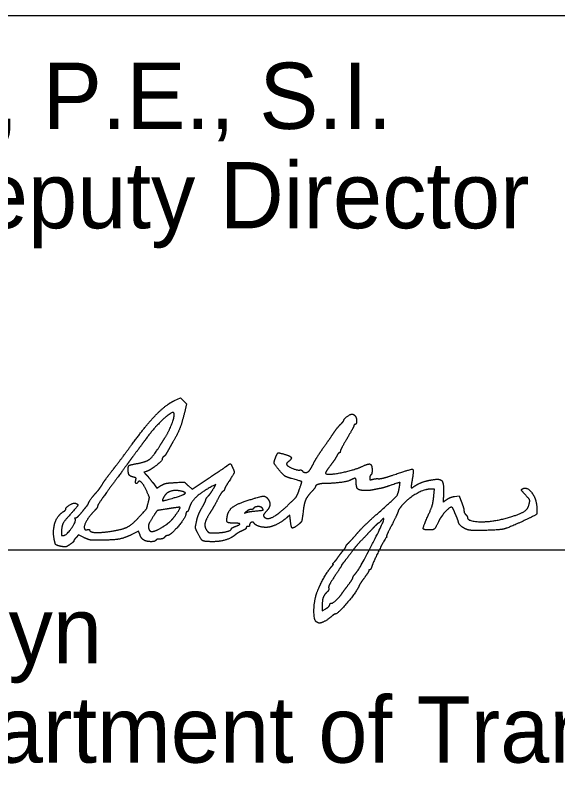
# Model space of a CAD drawing. Extents: x 0 to 42, y 0 to 22.
# Drawn here: x 25.676 to 26.824, y 7.305 to 8.926 of the extents above; entities that cross this region are included whole.
import ezdxf

# ---------------------------------------------------------------- set-up
doc = ezdxf.new("R2010")
doc.units = 0
doc.layers.add('SH_Data', color=7, linetype='Continuous')
doc.layers.add('SH_Text', color=7, linetype='Continuous')

msp = doc.modelspace()

# ---------------------------------------------------------------- linework, layer by layer
at = {"layer": 'SH_Data'}
for p, q in [((24.5279, 8.9262), (28.0279, 8.9262)), ((24.5279, 7.7968), (28.0279, 7.7968))]:
    msp.add_line(p, q, dxfattribs=at)
at = {"layer": 'SH_Text'}
for points in [[(26.0131, 8.112), (26.0258, 8.1179), (26.0321, 8.1115), (26.0385, 8.1051), (26.0341, 8.0864)], [(25.9532, 7.962), (25.9482, 7.9605), (25.9534, 7.9553)], [(26.0422, 7.9323), (26.0503, 7.9247), (26.0866, 7.9488)], [(25.967, 7.9386), (25.9756, 7.9271), (25.9844, 7.9323)], [(26.0961, 7.9271), (26.1005, 7.935), (26.095, 7.9321)], [(26.5619, 7.9112), (26.5634, 7.925), (26.5556, 7.925)], [(26.6058, 7.9095), (26.6154, 7.9111), (26.6205, 7.8975)], [(26.2578, 7.8634), (26.2572, 7.8702), (26.2513, 7.8651)], [(25.9402, 7.8278), (25.9369, 7.8358), (25.923, 7.829)], [(25.8216, 7.8227), (25.8101, 7.8285), (25.805, 7.8227)], [(26.3256, 7.6773), (26.3256, 7.6679), (26.3331, 7.6722)]]:
    msp.add_lwpolyline(points, dxfattribs=at)
for points in [[(25.9236, 8.0201), (25.9533, 8.0607), (25.9951, 8.1036), (26.0131, 8.112)], [(26.0117, 8.0862), (26.008, 8.0899), (25.9695, 8.0541), (25.9541, 8.0328)], [(25.9934, 8.0342), (26.0028, 8.049), (26.0148, 8.0831), (26.0117, 8.0862)], [(26.0341, 8.0864), (26.0291, 8.0653), (26.0199, 8.0417), (26.0105, 8.0258)], [(26.3712, 8.0701), (26.3712, 8.0729), (26.3844, 8.0832), (26.3881, 8.0833)], [(26.3881, 8.0833), (26.3901, 8.0833), (26.3931, 8.0821), (26.3947, 8.0805)], [(26.3947, 8.0805), (26.3982, 8.077), (26.3986, 8.0618), (26.3952, 8.0618)], [(26.3508, 8.0448), (26.3547, 8.0506), (26.361, 8.0583), (26.3646, 8.062)], [(26.3646, 8.062), (26.3682, 8.0656), (26.3712, 8.0693), (26.3712, 8.0701)], [(26.3952, 8.0618), (26.3939, 8.0618), (26.3928, 8.0606), (26.3928, 8.0592)], [(26.3292, 8.0138), (26.3371, 8.025), (26.3468, 8.0389), (26.3508, 8.0448)], [(26.3928, 8.0592), (26.3928, 8.0579), (26.3863, 8.0458), (26.3784, 8.0324)], [(25.9541, 8.0328), (25.9505, 8.0279), (25.9411, 8.0152), (25.9332, 8.0047)], [(25.9829, 8.0175), (25.9861, 8.0227), (25.9909, 8.0302), (25.9934, 8.0342)], [(26.3784, 8.0324), (26.3705, 8.019), (26.364, 8.0066), (26.364, 8.0049)], [(25.8834, 7.9667), (25.8923, 7.978), (25.9104, 8.0021), (25.9236, 8.0201)], [(25.9331, 7.9788), (25.9537, 7.9826), (25.9677, 7.9935), (25.9829, 8.0175)], [(26.0105, 8.0258), (26.007, 8.0198), (26.0018, 8.0106), (25.9989, 8.0054)], [(26.3078, 7.9802), (26.3116, 7.9874), (26.3212, 8.0025), (26.3292, 8.0138)], [(25.9332, 8.0047), (25.9253, 7.9942), (25.9172, 7.9832), (25.9152, 7.9803)], [(25.9989, 8.0054), (25.9961, 8.0001), (25.9923, 7.9949), (25.9905, 7.9938)], [(26.2271, 7.992), (26.2309, 8.0011), (26.234, 8.0021), (26.2467, 7.9983)], [(26.2467, 7.9983), (26.2587, 7.9948), (26.2616, 7.9886), (26.2539, 7.9828)], [(26.3567, 7.9952), (26.3549, 7.9915), (26.3488, 7.9824), (26.3431, 7.975)], [(26.362, 8.0018), (26.3609, 8.0018), (26.3585, 7.9988), (26.3567, 7.9952)], [(26.364, 8.0049), (26.364, 8.0032), (26.3631, 8.0018), (26.362, 8.0018)], [(25.9152, 7.9803), (25.9132, 7.9773), (25.8978, 7.9564), (25.881, 7.9337)], [(25.9152, 7.9667), (25.9152, 7.9736), (25.9193, 7.9764), (25.9331, 7.9788)], [(25.9872, 7.9884), (25.9872, 7.9847), (25.9614, 7.9646), (25.9532, 7.962)], [(25.9905, 7.9938), (25.9887, 7.9928), (25.9872, 7.9904), (25.9872, 7.9884)], [(26.1257, 7.9753), (26.1302, 7.9791), (26.1326, 7.9782), (26.1356, 7.9716)], [(26.2369, 7.9626), (26.2254, 7.9757), (26.2232, 7.9824), (26.2271, 7.992)], [(26.2539, 7.9828), (26.2512, 7.9807), (26.2497, 7.9778), (26.2506, 7.9765)], [(26.2985, 7.964), (26.2998, 7.9656), (26.304, 7.9729), (26.3078, 7.9802)], [(25.8619, 7.9373), (25.8648, 7.9421), (25.8745, 7.9553), (25.8834, 7.9667)], [(25.9262, 7.9503), (25.919, 7.9521), (25.9152, 7.9578), (25.9152, 7.9667)], [(26.0866, 7.9488), (26.1065, 7.9621), (26.1241, 7.974), (26.1257, 7.9753)], [(26.1356, 7.9716), (26.14, 7.962), (26.139, 7.9579), (26.1288, 7.942)], [(26.2604, 7.9474), (26.2496, 7.9506), (26.2447, 7.9537), (26.2369, 7.9626)], [(26.2506, 7.9765), (26.2533, 7.9727), (26.2732, 7.9645), (26.2778, 7.9653)], [(26.2778, 7.9653), (26.2801, 7.9657), (26.2827, 7.9649), (26.2835, 7.9635)], [(26.2835, 7.9635), (26.2857, 7.96), (26.2957, 7.9603), (26.2985, 7.964)], [(26.3431, 7.975), (26.3374, 7.9675), (26.3328, 7.9602), (26.3328, 7.9589)], [(26.3328, 7.9589), (26.3328, 7.9536), (26.3924, 7.9646), (26.4104, 7.9731)], [(26.4104, 7.9731), (26.4233, 7.9793), (26.4312, 7.9762), (26.4312, 7.9648)], [(26.4312, 7.9648), (26.4312, 7.9602), (26.4301, 7.9558), (26.4288, 7.955)], [(26.4735, 7.954), (26.5139, 7.9679), (26.5198, 7.9663), (26.5157, 7.9424)], [(25.9313, 7.9441), (25.9322, 7.9476), (25.9309, 7.9491), (25.9262, 7.9503)], [(25.9534, 7.9553), (25.9562, 7.9525), (25.9623, 7.945), (25.967, 7.9386)], [(26.2772, 7.9237), (26.2828, 7.9405), (26.2825, 7.9411), (26.2604, 7.9474)], [(26.3976, 7.9396), (26.3976, 7.9469), (26.3939, 7.9485), (26.3861, 7.9443)], [(26.4288, 7.955), (26.4275, 7.9541), (26.4264, 7.9513), (26.4264, 7.9487)], [(26.4264, 7.9487), (26.4264, 7.9447), (26.4274, 7.9442), (26.4318, 7.9456)], [(26.4318, 7.9456), (26.4348, 7.9465), (26.4406, 7.9472), (26.4447, 7.947)], [(26.4447, 7.947), (26.4489, 7.9468), (26.4618, 7.95), (26.4735, 7.954)], [(25.8456, 7.9154), (25.8522, 7.9228), (25.8564, 7.9285), (25.8619, 7.9373)], [(25.881, 7.9337), (25.8643, 7.9111), (25.8505, 7.8909), (25.8504, 7.889)], [(25.9355, 7.9393), (25.9331, 7.9354), (25.9299, 7.9389), (25.9313, 7.9441)], [(25.9543, 7.9207), (25.9482, 7.9344), (25.9385, 7.944), (25.9355, 7.9393)], [(25.9844, 7.9323), (25.9909, 7.9362), (25.9985, 7.9379), (26.0136, 7.9388)], [(26.0136, 7.9388), (26.0339, 7.94), (26.0341, 7.9399), (26.0422, 7.9323)], [(26.095, 7.9321), (26.0716, 7.9195), (26.0488, 7.8989), (26.0447, 7.8864)], [(26.1288, 7.942), (26.1235, 7.9339), (26.1192, 7.9263), (26.1192, 7.9252)], [(26.3354, 7.937), (26.3239, 7.937), (26.3112, 7.9332), (26.3112, 7.9298)], [(26.3861, 7.9443), (26.3806, 7.9413), (26.3504, 7.937), (26.3354, 7.937)], [(26.4169, 7.922), (26.4045, 7.922), (26.3976, 7.9283), (26.3976, 7.9396)], [(26.4682, 7.9321), (26.4604, 7.9294), (26.4507, 7.9266), (26.4468, 7.926)], [(26.4888, 7.9274), (26.4909, 7.9389), (26.4891, 7.9393), (26.4682, 7.9321)], [(26.5157, 7.9424), (26.5143, 7.9348), (26.5136, 7.9282), (26.5141, 7.9277)], [(26.5141, 7.9277), (26.5145, 7.9272), (26.5179, 7.929), (26.5216, 7.9316)], [(26.5216, 7.9316), (26.5289, 7.9366), (26.5471, 7.9429), (26.5608, 7.9451)], [(26.5608, 7.9451), (26.5754, 7.9474), (26.5831, 7.937), (26.5823, 7.9157)], [(25.8312, 7.895), (25.8312, 7.8966), (25.8403, 7.9096), (25.8456, 7.9154)], [(25.9576, 7.8962), (25.9602, 7.906), (25.9599, 7.9082), (25.9543, 7.9207)], [(26.0254, 7.921), (26.0145, 7.9232), (25.9971, 7.9181), (25.9928, 7.9115)], [(26.0148, 7.9075), (26.034, 7.9134), (26.038, 7.9185), (26.0254, 7.921)], [(26.0833, 7.9089), (26.0887, 7.9149), (26.0912, 7.9185), (26.0961, 7.9271)], [(26.1156, 7.9202), (26.1137, 7.9186), (26.1106, 7.9144), (26.1087, 7.9109)], [(26.1192, 7.9252), (26.1192, 7.9241), (26.1176, 7.9218), (26.1156, 7.9202)], [(26.2589, 7.8964), (26.2693, 7.9064), (26.2734, 7.9126), (26.2772, 7.9237)], [(26.3018, 7.9177), (26.2933, 7.9083), (26.2876, 7.8957), (26.286, 7.883)], [(26.3112, 7.9298), (26.3112, 7.9289), (26.307, 7.9235), (26.3018, 7.9177)], [(26.4336, 7.9234), (26.4303, 7.9226), (26.4228, 7.922), (26.4169, 7.922)], [(26.4468, 7.926), (26.4428, 7.9253), (26.4369, 7.9242), (26.4336, 7.9234)], [(26.4439, 7.8744), (26.4795, 7.906), (26.4864, 7.9142), (26.4888, 7.9274)], [(26.5556, 7.925), (26.5429, 7.925), (26.5091, 7.9065), (26.4969, 7.893)], [(26.5823, 7.9157), (26.5816, 7.8973), (26.5815, 7.8976), (26.5892, 7.9031)], [(26.7524, 7.9163), (26.7471, 7.922), (26.7468, 7.9247), (26.7515, 7.9264)], [(26.7515, 7.9264), (26.76, 7.9297), (26.7785, 7.9048), (26.7795, 7.8885)], [(26.7615, 7.8872), (26.7655, 7.899), (26.7639, 7.9039), (26.7524, 7.9163)], [(25.9928, 7.9115), (25.9858, 7.9008), (25.9903, 7.9), (26.0148, 7.9075)], [(26.0708, 7.8848), (26.0752, 7.8925), (26.079, 7.9002), (26.0793, 7.9019)], [(26.0793, 7.9019), (26.0796, 7.9037), (26.0813, 7.9068), (26.0833, 7.9089)], [(26.1087, 7.9109), (26.1006, 7.8955), (26.0928, 7.8817), (26.0867, 7.872)], [(26.1249, 7.8681), (26.1271, 7.8794), (26.1433, 7.8928), (26.1626, 7.8992)], [(26.1626, 7.8992), (26.1944, 7.9098), (26.2078, 7.9102), (26.2129, 7.9008)], [(26.2129, 7.9008), (26.2161, 7.8947), (26.2127, 7.8833), (26.2053, 7.8754)], [(26.5472, 7.8633), (26.5563, 7.8832), (26.5603, 7.8964), (26.5619, 7.9112)], [(26.5892, 7.9031), (26.593, 7.9058), (26.6004, 7.9087), (26.6058, 7.9095)], [(26.6205, 7.8975), (26.6233, 7.8901), (26.6256, 7.8819), (26.6256, 7.8794)], [(25.7785, 7.8776), (25.7811, 7.8792), (25.7832, 7.8816), (25.7832, 7.8829)], [(25.7832, 7.8829), (25.7833, 7.8867), (25.8, 7.8967), (25.8038, 7.8952)], [(25.8038, 7.8952), (25.8098, 7.8929), (25.8075, 7.888), (25.7932, 7.8721)], [(25.8167, 7.8758), (25.822, 7.8824), (25.8275, 7.8891), (25.8288, 7.8907)], [(25.8288, 7.8907), (25.8301, 7.8923), (25.8312, 7.8942), (25.8312, 7.895)], [(25.8504, 7.889), (25.8503, 7.887), (25.847, 7.8822), (25.843, 7.8782)], [(25.938, 7.8657), (25.9541, 7.8832), (25.9544, 7.8838), (25.9576, 7.8962)], [(25.9956, 7.8827), (25.9778, 7.8801), (25.9758, 7.879), (25.9685, 7.8678)], [(26.013, 7.8854), (26.0074, 7.8845), (25.9995, 7.8833), (25.9956, 7.8827)], [(26.018, 7.8737), (26.0258, 7.8851), (26.0249, 7.8872), (26.013, 7.8854)], [(26.0447, 7.8864), (26.043, 7.8812), (26.0407, 7.877), (26.0396, 7.877)], [(26.0599, 7.857), (26.0615, 7.8647), (26.0664, 7.8772), (26.0708, 7.8848)], [(26.1747, 7.8818), (26.1724, 7.8818), (26.1684, 7.88), (26.1658, 7.878)], [(26.1802, 7.8839), (26.1795, 7.8827), (26.177, 7.8818), (26.1747, 7.8818)], [(26.1987, 7.885), (26.1959, 7.8884), (26.1825, 7.8876), (26.1802, 7.8839)], [(26.1828, 7.8786), (26.1995, 7.8801), (26.2019, 7.8811), (26.1987, 7.885)], [(26.2019, 7.8675), (26.2072, 7.8589), (26.2339, 7.8724), (26.2589, 7.8964)], [(26.286, 7.883), (26.2832, 7.8605), (26.2814, 7.855), (26.2758, 7.8505)], [(26.4969, 7.893), (26.4911, 7.8865), (26.4864, 7.88), (26.4864, 7.8784)], [(26.5988, 7.8866), (26.5945, 7.8866), (26.5762, 7.8661), (26.5715, 7.8559)], [(26.6044, 7.88), (26.6029, 7.8836), (26.6004, 7.8866), (26.5988, 7.8866)], [(26.7126, 7.863), (26.7363, 7.8692), (26.7593, 7.8806), (26.7615, 7.8872)], [(26.7795, 7.8885), (26.7804, 7.8732), (26.7778, 7.8701), (26.7544, 7.8591)], [(25.7583, 7.8213), (25.7554, 7.8398), (25.7661, 7.8699), (25.7785, 7.8776)], [(25.7932, 7.8721), (25.7795, 7.857), (25.7745, 7.8468), (25.7739, 7.833)], [(25.8044, 7.8645), (25.8058, 7.8641), (25.8113, 7.8692), (25.8167, 7.8758)], [(25.843, 7.8782), (25.8332, 7.8686), (25.8208, 7.8465), (25.8226, 7.8418)], [(25.8815, 7.8363), (25.9042, 7.84), (25.9238, 7.8502), (25.938, 7.8657)], [(25.9685, 7.8678), (25.9603, 7.8551), (25.9571, 7.8453), (25.9593, 7.8395)], [(25.9881, 7.845), (25.9993, 7.852), (26.0102, 7.8626), (26.018, 7.8737)], [(26.0375, 7.874), (26.0374, 7.8654), (26.0043, 7.8266), (25.9972, 7.8266)], [(26.0396, 7.877), (26.0385, 7.877), (26.0376, 7.8756), (26.0375, 7.874)], [(26.0867, 7.872), (26.0787, 7.8594), (26.0765, 7.8442), (26.0816, 7.8374)], [(26.1385, 7.853), (26.127, 7.853), (26.1229, 7.8575), (26.1249, 7.8681)], [(26.1658, 7.878), (26.1612, 7.8742), (26.1612, 7.8742), (26.166, 7.8759)], [(26.166, 7.8759), (26.1686, 7.8768), (26.1762, 7.878), (26.1828, 7.8786)], [(26.2053, 7.8754), (26.2025, 7.8725), (26.201, 7.869), (26.2019, 7.8675)], [(26.2513, 7.8651), (26.2419, 7.8569), (26.2219, 7.8463), (26.2128, 7.8446)], [(26.3999, 7.8317), (26.4071, 7.8401), (26.4269, 7.8593), (26.4439, 7.8744)], [(26.4864, 7.8784), (26.4864, 7.8768), (26.4804, 7.864), (26.4732, 7.8498)], [(26.6103, 7.8658), (26.6085, 7.87), (26.6058, 7.8763), (26.6044, 7.88)], [(26.6137, 7.8562), (26.6136, 7.8573), (26.6121, 7.8616), (26.6103, 7.8658)], [(26.6256, 7.8794), (26.6256, 7.8769), (26.6272, 7.8733), (26.6292, 7.8713)], [(26.6292, 7.8713), (26.6312, 7.8693), (26.6328, 7.8666), (26.6328, 7.8653)], [(26.6328, 7.8653), (26.6328, 7.8568), (26.6834, 7.8553), (26.7126, 7.863)], [(25.7787, 7.827), (25.7851, 7.8279), (25.8052, 7.8564), (25.8032, 7.8616)], [(25.8032, 7.8616), (25.8024, 7.8635), (25.803, 7.8648), (25.8044, 7.8645)], [(26.0619, 7.833), (26.0575, 7.8421), (26.0573, 7.8443), (26.0599, 7.857)], [(26.1419, 7.846), (26.1522, 7.8498), (26.1506, 7.853), (26.1385, 7.853)], [(26.172, 7.8491), (26.172, 7.8473), (26.1704, 7.8458), (26.1684, 7.8458)], [(26.1815, 7.8531), (26.1795, 7.8564), (26.172, 7.8532), (26.172, 7.8491)], [(26.2128, 7.8446), (26.2042, 7.8431), (26.1844, 7.8484), (26.1815, 7.8531)], [(26.2758, 7.8505), (26.264, 7.8413), (26.2597, 7.8444), (26.2578, 7.8634)], [(26.3973, 7.7479), (26.4049, 7.7566), (26.4582, 7.8604), (26.4561, 7.8624)], [(26.4446, 7.853), (26.4438, 7.853), (26.4399, 7.8494), (26.4358, 7.8452)], [(26.4504, 7.8584), (26.448, 7.8554), (26.4454, 7.853), (26.4446, 7.853)], [(26.4561, 7.8624), (26.4554, 7.8632), (26.4528, 7.8613), (26.4504, 7.8584)], [(26.4732, 7.8498), (26.4659, 7.8357), (26.4607, 7.8241), (26.4618, 7.8241)], [(26.5546, 7.8386), (26.5401, 7.8386), (26.5385, 7.844), (26.5472, 7.8633)], [(26.5715, 7.8559), (26.5658, 7.8435), (26.5609, 7.8386), (26.5546, 7.8386)], [(26.6293, 7.8406), (26.6223, 7.844), (26.6138, 7.8524), (26.6137, 7.8562)], [(26.7544, 7.8591), (26.7196, 7.8428), (26.6985, 7.838), (26.6592, 7.8376)], [(25.7739, 7.833), (25.7737, 7.8274), (25.7745, 7.8264), (25.7787, 7.827)], [(25.8226, 7.8418), (25.8235, 7.8394), (25.8258, 7.8385), (25.8288, 7.8393)], [(25.8288, 7.8393), (25.8314, 7.8399), (25.8336, 7.8396), (25.8336, 7.8385)], [(25.8336, 7.8385), (25.8336, 7.8339), (25.8592, 7.8327), (25.8815, 7.8363)], [(25.9593, 7.8395), (25.9614, 7.8342), (25.9749, 7.8369), (25.9881, 7.845)], [(26.0937, 7.8138), (26.0762, 7.8139), (26.0692, 7.8182), (26.0619, 7.833)], [(26.0816, 7.8374), (26.0844, 7.8336), (26.088, 7.8326), (26.0992, 7.8326)], [(26.0992, 7.8326), (26.1132, 7.8326), (26.1336, 7.8377), (26.1336, 7.8412)], [(26.1336, 7.8412), (26.1336, 7.8422), (26.1373, 7.8444), (26.1419, 7.846)], [(26.1594, 7.8384), (26.152, 7.8351), (26.1444, 7.8306), (26.1402, 7.8271)], [(26.1648, 7.8433), (26.1648, 7.8419), (26.1624, 7.8397), (26.1594, 7.8384)], [(26.1684, 7.8458), (26.1664, 7.8458), (26.1648, 7.8447), (26.1648, 7.8433)], [(26.4358, 7.8452), (26.4317, 7.8409), (26.4212, 7.8298), (26.4124, 7.8205)], [(26.6592, 7.8376), (26.6442, 7.8374), (26.6339, 7.8385), (26.6293, 7.8406)], [(25.7749, 7.8036), (25.764, 7.8056), (25.7602, 7.8097), (25.7583, 7.8213)], [(25.805, 7.8227), (25.8022, 7.8195), (25.8, 7.8161), (25.8, 7.8151)], [(25.8524, 7.817), (25.8368, 7.817), (25.8309, 7.8181), (25.8216, 7.8227)], [(25.923, 7.829), (25.9074, 7.8212), (25.8823, 7.817), (25.8524, 7.817)], [(25.9484, 7.8172), (25.9458, 7.8186), (25.9421, 7.8234), (25.9402, 7.8278)], [(25.974, 7.817), (25.972, 7.8138), (25.9545, 7.8139), (25.9484, 7.8172)], [(25.9822, 7.8194), (25.9785, 7.8194), (25.9748, 7.8183), (25.974, 7.817)], [(25.992, 7.823), (25.9903, 7.821), (25.9859, 7.8194), (25.9822, 7.8194)], [(25.9972, 7.8266), (25.996, 7.8266), (25.9936, 7.8249), (25.992, 7.823)], [(26.1402, 7.8271), (26.1325, 7.8207), (26.1082, 7.8138), (26.0937, 7.8138)], [(26.3814, 7.8113), (26.3844, 7.8141), (26.3927, 7.8233), (26.3999, 7.8317)], [(26.4124, 7.8205), (26.4036, 7.8113), (26.3937, 7.8), (26.3904, 7.7955)], [(26.461, 7.8223), (26.4583, 7.8205), (26.4331, 7.7695), (26.4301, 7.76)], [(26.4618, 7.8241), (26.4628, 7.8241), (26.4624, 7.8233), (26.461, 7.8223)], [(25.7916, 7.8077), (25.7851, 7.8032), (25.7815, 7.8023), (25.7749, 7.8036)], [(25.8, 7.8151), (25.8, 7.8142), (25.7962, 7.8108), (25.7916, 7.8077)], [(26.3694, 7.7943), (26.373, 7.7985), (26.376, 7.8029), (26.376, 7.8041)], [(26.376, 7.8041), (26.376, 7.8052), (26.3785, 7.8085), (26.3814, 7.8113)], [(26.3592, 7.7809), (26.3612, 7.784), (26.3658, 7.79), (26.3694, 7.7943)], [(26.3904, 7.7955), (26.3823, 7.7846), (26.3718, 7.7708), (26.3688, 7.7673)], [(26.3488, 7.7666), (26.3479, 7.7666), (26.3491, 7.7685), (26.3514, 7.771)], [(26.3514, 7.771), (26.3537, 7.7734), (26.3572, 7.7779), (26.3592, 7.7809)], [(26.3154, 7.7086), (26.3213, 7.7234), (26.3384, 7.7533), (26.3455, 7.7612)], [(26.3455, 7.7612), (26.3482, 7.7641), (26.3497, 7.7666), (26.3488, 7.7666)], [(26.3664, 7.7634), (26.3664, 7.7628), (26.36, 7.7529), (26.3523, 7.7413)], [(26.3688, 7.7673), (26.3675, 7.7657), (26.3664, 7.7639), (26.3664, 7.7634)], [(26.424, 7.7521), (26.424, 7.7507), (26.4197, 7.7439), (26.4145, 7.737)], [(26.4262, 7.7546), (26.425, 7.7546), (26.424, 7.7534), (26.424, 7.7521)], [(26.4301, 7.76), (26.4292, 7.757), (26.4274, 7.7546), (26.4262, 7.7546)], [(26.3523, 7.7413), (26.3436, 7.7282), (26.3387, 7.7185), (26.3394, 7.7158)], [(26.3802, 7.7217), (26.3858, 7.7291), (26.3904, 7.7362), (26.3904, 7.7376)], [(26.3904, 7.7376), (26.3904, 7.7389), (26.3935, 7.7435), (26.3973, 7.7479)], [(26.4145, 7.737), (26.4093, 7.7301), (26.4042, 7.7221), (26.4031, 7.7193)], [(26.4031, 7.7193), (26.3994, 7.7094), (26.3583, 7.661), (26.3536, 7.661)], [(26.3676, 7.7045), (26.3689, 7.7066), (26.3746, 7.7144), (26.3802, 7.7217)], [(26.3136, 7.6441), (26.3076, 7.6479), (26.3089, 7.6922), (26.3154, 7.7086)], [(26.3357, 7.7072), (26.3298, 7.7019), (26.3256, 7.6896), (26.3256, 7.6773)], [(26.3394, 7.7158), (26.34, 7.7132), (26.3385, 7.7096), (26.3357, 7.7072)], [(26.3448, 7.6838), (26.3467, 7.6826), (26.3633, 7.6977), (26.3676, 7.7045)], [(26.3331, 7.6722), (26.3373, 7.6746), (26.3412, 7.6784), (26.3418, 7.6807)], [(26.3418, 7.6807), (26.3424, 7.683), (26.3438, 7.6844), (26.3448, 7.6838)], [(26.3461, 7.6564), (26.3399, 7.6507), (26.324, 7.6417), (26.3201, 7.6418)], [(26.3536, 7.661), (26.3522, 7.661), (26.3489, 7.6589), (26.3461, 7.6564)], [(26.3201, 7.6418), (26.3185, 7.6418), (26.3156, 7.6429), (26.3136, 7.6441)]]:
    msp.add_open_spline(points, degree=2, dxfattribs=at)

# ---------------------------------------------------------------- texts
for s, p in [('Pat McColley, P.E., S.I.', (24.5279, 8.6862)), ('District       Deputy Director', (24.5279, 8.4762)), ('Pamela Boratyn', (24.5279, 7.5568)), ('Director, Department of Transportation', (24.5279, 7.3468))]:
    msp.add_text(s, height=0.14, dxfattribs=at).set_placement(p)

doc.saveas('drawing.dxf')
